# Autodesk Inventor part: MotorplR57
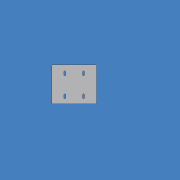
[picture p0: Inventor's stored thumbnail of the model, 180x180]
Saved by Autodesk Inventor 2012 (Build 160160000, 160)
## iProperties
Company: CAD-Verlag
Shininess: 64.0
Length Units: 11269
Angle Units: 11279
Time Units: 11290
Mass Units: 11283
Length Display Precision: 3
Angle Display Precision: 2
Compacted: True
Part Number: MotorplR57
Document SubType Name: Modeling
Created: 2004-09
Material: Standard
Designer: Greiling
Manufacturer: Standard
Standards Organization: Custom
Density: 1 g/cm^3
Density: 0.0
Volumn: 0.0
Area: 0.0
PropertySet Name: Model Information
Control State: 0
Master: False
Checked Out: False
Author: Jürgen Kronas
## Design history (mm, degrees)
sketch "Skizze1"
  geometry: L1 (0, 224)-(0, -168) reference; L2 (-192, 0)-(256, 0) reference; L3 (-192, 0)-(256, 0) reference; L4 (0, -168)-(0, 224) reference; L5 (-160, 140)-(160, 140); L6 (160, 140)-(160, -140); L7 (160, -140)-(-160, -140); L8 (-160, -140)-(-160, 140); 1 further point
  constraints: 8 end point, 2 parallel, 1 horizontal, 1 perpendicular, 2 other
  dimensions: "d0" = 280 distance of L7.end L5.start; "d1" = 320 distance of L5.start L5.end
extrude "Extrusion1" new body sketch "Skizze1" distance "d2" = 10; taper "d3" = 0 deg
sketch "Skizze2"
  geometry: L1 (-160, 140)-(160, 140) reference; L2 (0, 224)-(0, -168) reference; L3 (-192, 0)-(256, 0) reference; L4 (-192, 0)-(256, 0) reference; L5 (0, -168)-(0, 224) reference; L6 (-74.5, 90.5)-(-74.5, 69.174); L7 (-60.5, 90.5)-(-60.5, 69.174); L8 (74.5, 90.5)-(74.5, 69.174); L9 (60.5, 90.5)-(60.5, 69.174); L10 (-60.5, -74.5)-(-60.5, -95.826); L11 (-74.5, -74.5)-(-74.5, -95.826); L12 (74.5, -74.5)-(74.5, -95.826); L13 (60.5, -74.5)-(60.5, -95.826); A1 r 7 centre (-67.5, 90.5) between (-60.5, 90.5) and (-74.5, 90.5); A2 r 7 centre (-67.5, 69.174) between (-74.5, 69.174) and (-60.5, 69.174); A3 r 7 centre (67.5, 90.5) between (74.5, 90.5) and (60.5, 90.5); A4 r 7 centre (67.5, 69.174) between (60.5, 69.174) and (74.5, 69.174); A5 r 7 centre (-67.5, -74.5) between (-60.5, -74.5) and (-74.5, -74.5); A6 r 7 centre (-67.5, -95.826) between (-74.5, -95.826) and (-60.5, -95.826); A7 r 7 centre (67.5, -74.5) between (74.5, -74.5) and (60.5, -74.5); A8 r 7 centre (67.5, -95.826) between (60.5, -95.826) and (74.5, -95.826); 9 further points
  constraints: 16 end point, 16 point on circle, 8 centre point, 8 tangent, 4 coincident, 1 horizontal, 1 vertical, 36 other
  dimensions: "d4" = 49.5 distance from line of L1 point (-67.5, 90.5); "d5" = 16 distance of point (-67.5, 74.5) point (-67.5, 90.5); "d6" = 67.5 distance from line of L2 point (-67.5, 90.5); "d7" = 67.5 distance from line of L2 point (-67.5, 74.5); "d8" = 14 diameter of A2; "d9" = 14 diameter of A1; "d13" = 135 distance of A1.centre A3.centre; "d16" = 165 distance of A1.centre A5.centre
extrude "Extrusion2" cut sketch "Skizze2" distance "d19" = 10; taper "d20" = 0 deg
node "Volumenkörper1"
node "Volumenkörpern"
node "Oberflächenkörpern"
